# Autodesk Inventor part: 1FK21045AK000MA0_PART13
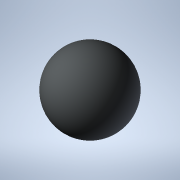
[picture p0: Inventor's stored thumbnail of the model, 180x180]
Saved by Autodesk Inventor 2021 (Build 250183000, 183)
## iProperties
Created: 2025-04
Part Number: 1FK21045AK000MA0_PART13
Material: Generic
Catalog Web Link: www.3dfindit.com
Description: -Servo synchronous motor
Document SubType Name: Modeling
Designer: psAdmin
Mass: 0.137258 g
Surface Area: 1.2868 cm^2
Volume: 0.137258 cm^3
Density: 1 g/cm^3
Appearance: PSOLRGB-212-217-219
Category: PARTsolutions
Title: 1FK21045AK000MA0_PART13
Author: Cadenas PARTsolutions
Comments: Servo synchronous motor
Sending System: PARTsolutions
Preprocessor: ST-DEVELOPER v19.3
PSOL_IDENT_0: {$CADENAS_DATA/23d-libs/siemens_ag/_cat_/3d/2f/1fk21045ak000ma0.prj},216 {VTYP=3D},{NB=1FK21045AK000
PSOL_IDENT_1: MA0_PART13},{LINA=1FK21045AK000MA0_PART13},{NN=1FK21045AK000MA0_PART13},{NOPRJ=TRUE},{DATE=19.08.202
PSOL_IDENT_2: 5 14:00:34},{GEOMDATE=30.07.2025 02:01:24},{VERSION=},{LINEID=10},{WBVAR=},{WBNUMERIC=}  {NB=1FK2104
PSOL_IDENT_3: 5AK000MA0_PART13},{LINA=1FK21045AK000MA0_PART13},{KT=DUMMY},{PREVIEW=../../../_pool_/a9/69/p_d211_xx
PSOL_IDENT_4: _00818j.png},{DESCSHORT=SIMOTICS S-1FK2 HD, SINAMICS S210 3AC 400V-480V, 1.7 Nm, 6000 rpm},{DESCLONG=
PSOL_IDENT_5: SIMOTICS S-1FK2 HD servo motor M0=2.4 Nm; PN = 1.07 kW at nN=6000 rpm (380-480 V); PN = 0.75 kW at n
PSOL_IDENT_6: N=3000 rpm (200-240 V); degree of protection IP64; cylindrical shaft D19x40mm; absolute encoder 22-b
PSOL_IDENT_7: it + 12-bit multiturn (encoder AM22DQC); with OCC interface; plug size M17, rotatable; SIMOTICS S-1F
PSOL_IDENT_8: K2 servomotorfor a wide range of uses in industrial environments. SIMOTICS S‑1FK2 servomotors are co
PSOL_IDENT_9: mpact synchronous motors with a high dynamic performance that set themselves apart as a result of th
PSOL_IDENT_10: eir high power density, degree of protection and overload capability. The motors are available in tw
PSOL_IDENT_11: o variants: as High Dynamic variant (highest dynamic performance as a result of the low intrinsic mo
PSOL_IDENT_12: ment of inertia for applications demanding a high dynamic performance with low moved masses) - and a
PSOL_IDENT_13: s Compact variant (precise and stable closed-loop control for medium up to large moved masses as a r
PSOL_IDENT_14: esult of a medium intrinsic moment of inertia). SIMOTICSS‑1FK2 servomotors fully exploit their stren
PSOL_IDENT_15: gths in a system with the SINAMICSS210 frequency converter and simple connection using the one cable
PSOL_IDENT_16: connection (OCC). Advantages include the short control and positioning times, fast and precise corr
PSOL_IDENT_17: ection of disturbing quantities as well as stable control with a high dynamic performance. The servo
PSOL_IDENT_18: motors can be configured to address a wide range of requirements. For example with and without hold
PSOL_IDENT_19: ing brake, IP64 or IP65 degree of protection, singleturn or multiturn absolute encoders - to name ju
PSOL_IDENT_20: st a few. Further, the servomotors are available in different shaft heights extending from 20 to 100
PSOL_IDENT_21: . A shaft sealing ring is available to achieve an IP65 degree of protection and for subsequent mount
PSOL_IDENT_22: ing at the motor or as spare part. SIMOTICS - the optimum motor for each and every motion control ap
PSOL_IDENT_23: plication.},{INTNO=804766789342},{SUPPLIERALTNO=1FK2104-5AK00-0MA0},{MANUID=1FK21045AK000MA0},{MANUN
PSOL_IDENT_24: AME=Siemens},{MANUTYPEDESC=Synchronous motor 1FK2-HD 2,39 Nm},{AAU732=SIMOTICS},{AAO057=S-1FK2},{AAU
PSOL_IDENT_25: 734=SIMOTICS S-1FK2 HD servo motor M0=2.4 Nm; PN = 1.07 kW at nN=6000 rpm (380-480 V); PN = 0.75 kW
PSOL_IDENT_26: at nN=3000 rpm (200-240 V); degree of protection IP64; cylindrical shaft D19x40mm; absolute encoder
PSOL_IDENT_27: 22-bit + 12-bit multiturn (encoder AM22DQC); with OCC interface; plug size M17, rotatable;},{AAW338=
PSOL_IDENT_28: Synchronous motor 1FK2-HD 2,39 Nm},{AAO742=SIMOTICS},{AAO663=4042948691151},{NOCUPEROU=1},{PRICEQUAN
PSOL_IDENT_29: TITY=1},{QUANTITYMIN=1},{QUANTITYINT=1},{CTN=85015100},{COO=DE},{AAO676=1FK2104-5AK00-0MA0},{AAO677=
PSOL_IDENT_30: Siemens AG},{ORDERUNIT=C62},{CONTENTUNIT=C62}
NB: 1FK21045AK000MA0_PART13
NT: Servo synchronous motor
NBSYN: $MANUID._PART13
LINA: 1FK21045AK000MA0_PART13
CATALOG: SIEMENS
PREVIEW: ../../../_pool_/a9/69/p_d211_xx_00818j.png
DESCSHORT: SIMOTICS S-1FK2 HD, SINAMICS S210 3AC 400V-480V, 1.7 Nm, 6000 rpm
DESCLONG: SIMOTICS S-1FK2 HD servo motor M0=2.4 Nm; PN = 1.07 kW at nN=6000 rpm (380-480 V); PN = 0.75 kW at nN=3000 rpm (200-240 V); degree of protection IP64; cylindric
INTNO: 804766789342
SUPPLIERALTNO: 1FK2104-5AK00-0MA0
MANUID: 1FK21045AK000MA0
MANUNAME: Siemens
MANUTYPEDESC: Synchronous motor 1FK2-HD 2,39 Nm
AAU732: SIMOTICS
AAO057: S-1FK2
AAU734: SIMOTICS S-1FK2 HD servo motor M0=2.4 Nm; PN = 1.07 kW at nN=6000 rpm (380-480 V); PN = 0.75 kW at nN=3000 rpm (200-240 V); degree of protection IP64; cylindric
AAW338: Synchronous motor 1FK2-HD 2,39 Nm
AAO742: SIMOTICS
AAO663: 4042948691151.0
NOCUPEROU: 1
PRICEQUANTITY: 1
QUANTITYMIN: 1
QUANTITYINT: 1
CTN: 85015100
COO: DE
ARTICLENO: 1FK21045AK000MA0_PART13
BOMINFO: 1FK21045AK000MA0_PART13
CREATOR: CADENAS GmbH
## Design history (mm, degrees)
feature "2025_04_17_15_39_51_0728"
body "Solid1"
